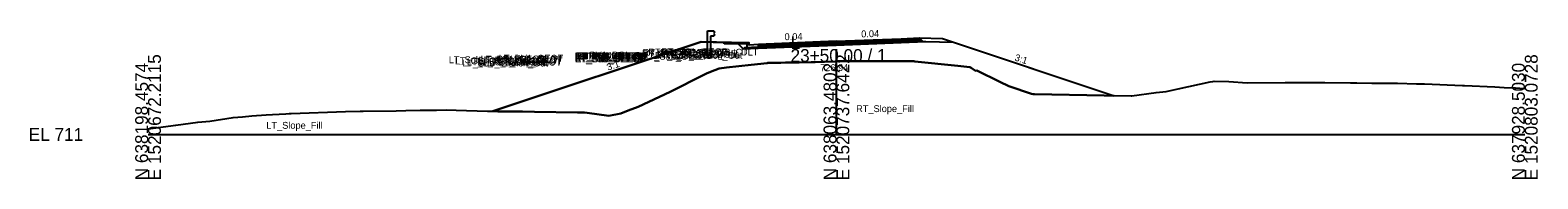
# Model space of a CAD drawing. Extents: x -26 to 3903, y -10 to 9531.
# Drawn here: x 974.3 to 1302.8, y 3490.3 to 3522.7 of the extents above; entities that cross this region are included whole.
import ezdxf

# ---------------------------------------------------------------- set-up
doc = ezdxf.new("R2010")
doc.units = 0
for name, color, linetype in [('Default', 7, 'Continuous'), ('Exist Cross Section Cell', 7, 'Continuous'), ('Exist XS Center Line Elevation Label', 7, 'Continuous'), ('Exist XS Ground Line', 7, 'Continuous'), ('Old_Level_63', 7, 'Continuous'), ('Prop CMT Conc Surface', 7, 'Continuous'), ('Prop CMT Guardrail Graphics', 7, 'Continuous'), ('Prop CMT Pvmt Course 1', 7, 'Continuous'), ('Prop CMT Pvmt Course 1 CG', 7, 'Continuous'), ('Prop CMT Pvmt Course 2', 7, 'Continuous'), ('Prop CMT Pvmt Course 3', 7, 'Continuous'), ('Prop CMT Pvmt Surface', 7, 'Continuous'), ('Prop CMT Pvmt Surface Shoulder', 7, 'Continuous'), ('Prop CMT Shld Paved Course 1', 7, 'Continuous'), ('Prop CMT Shld Paved Course 2', 7, 'Continuous'), ('Prop CMT Shld Paved Course 3', 7, 'Continuous'), ('Prop CMT Slope Grass', 7, 'Continuous'), ('Prop CMT Subgrade Earthwork', 7, 'Continuous'), ('Prop XS Earthwork Shape', 7, 'Continuous'), ('Prop XS Finish Grade Concrete', 7, 'Continuous'), ('Prop XS SE Text', 7, 'Continuous'), ('Prop XS Side Slope Text', 7, 'Continuous')]:
    doc.layers.add(name, color=color, linetype=linetype)

msp = doc.modelspace()

# ---------------------------------------------------------------- linework, layer by layer
at = {"layer": 'Exist Cross Section Cell'}
for p, q in [((1150, 3500), (1150, 3518.61)), ((1000, 3500), (1150, 3500)), ((1150, 3500), (1300, 3500))]:
    msp.add_line(p, q, dxfattribs=at)
at = {"layer": 'Exist XS Ground Line'}
msp.add_lwpolyline([(1000, 3501.2), (1006.06, 3502.04), (1010.87, 3502.66), (1013.43, 3502.91), (1018.58, 3503.68), (1020.58, 3503.83), (1022.59, 3504.07), (1025.76, 3504.25), (1027.11, 3504.34), (1030.01, 3504.49), (1030.72, 3504.53), (1031.16, 3504.55), (1042.99, 3504.97), (1046.22, 3505.08), (1046.5, 3505.1), (1046.84, 3505.1), (1054.04, 3505.17), (1056.16, 3505.22), (1059.32, 3505.26), (1062.82, 3505.3), (1065.04, 3505.34), (1067.17, 3505.32), (1073.96, 3505.09), (1074.47, 3505.07), (1075.61, 3505.05), (1076.21, 3504.99), (1081.61, 3504.99), (1084.22, 3504.94), (1093.59, 3504.81), (1095.09, 3504.8), (1095.69, 3504.69), (1100.44, 3504.03), (1103.05, 3504.6), (1104.65, 3505.19), (1106.77, 3506.03), (1113.74, 3509.28), (1121.12, 3513), (1121.81, 3513.39), (1123.53, 3514.03), (1124.47, 3514.39), (1126.04, 3514.59), (1131.41, 3515.19), (1134.91, 3515.57), (1135.05, 3515.58), (1135.54, 3515.6), (1135.84, 3515.6), (1136.08, 3515.61), (1136.12, 3515.62), (1136.35, 3515.62), (1137.86, 3515.64), (1138.9, 3515.66), (1139.73, 3515.67), (1141.48, 3515.7), (1141.62, 3515.7), (1141.7, 3515.7), (1141.9, 3515.71), (1144.46, 3515.77), (1145.36, 3515.79), (1147.19, 3515.85), (1147.23, 3515.85), (1147.25, 3515.85), (1147.4, 3515.86), (1149.82, 3515.94), (1149.93, 3515.95), (1150.16, 3515.95), (1152.79, 3515.96), (1152.9, 3515.96), (1155.55, 3515.96), (1158.04, 3515.98), (1158.32, 3515.98), (1158.41, 3515.98), (1158.61, 3515.98), (1160.29, 3515.97), (1161.11, 3515.97), (1163.46, 3515.98), (1163.89, 3515.98), (1163.93, 3515.98), (1164.31, 3515.97), (1165.32, 3515.97), (1166.69, 3515.96), (1166.83, 3515.96), (1167.06, 3515.94), (1176.42, 3514.99), (1179.08, 3514.64), (1179.33, 3514.54), (1180.31, 3513.85), (1180.58, 3513.97), (1185.58, 3511.49), (1187.55, 3510.52), (1192.54, 3508.86), (1192.76, 3508.81), (1193.17, 3508.79), (1208.34, 3508.46), (1214.24, 3508.43), (1214.35, 3508.43), (1219.67, 3509.11), (1221.85, 3509.35), (1224.5, 3509.91), (1231.41, 3511.45), (1231.99, 3511.57), (1232.28, 3511.63), (1235.47, 3511.56), (1239.5, 3511.27), (1247.81, 3511.36), (1251.2, 3511.35), (1256.37, 3511.36), (1256.39, 3511.36), (1262.02, 3511.25), (1263.4, 3511.23), (1266.66, 3511.2), (1268.29, 3511.19), (1272.27, 3511.16), (1276.41, 3511.05), (1278.15, 3511.01), (1286.39, 3510.68), (1286.83, 3510.66), (1293.46, 3510.36), (1293.5, 3510.36), (1295.47, 3510.26), (1297.88, 3510.14), (1297.99, 3510.13), (1298.91, 3510.09), (1300, 3510.04)], dxfattribs=at)
at = {"layer": 'Old_Level_63'}
for p, q in [((1131, 3519.47), (1131, 3519.97)), ((1133, 3519.63), (1131, 3519.47))]:
    msp.add_line(p, q, dxfattribs=at)
for points in [[(1125.5, 3519.75), (1125.5, 3520.07)], [(1130.5, 3519.65), (1125.5, 3519.75)], [(1130.5, 3519.97), (1130.5, 3518.95), (1133, 3519.05)], [(1133, 3519.05), (1133, 3519.63)]]:
    msp.add_lwpolyline(points, dxfattribs=at)
at = {"layer": 'Prop CMT Guardrail Graphics'}
for points in [[(1121.9, 3516.62), (1121.9, 3522.62)], [(1121.9, 3522.62), (1123.23, 3522.62), (1123.5, 3522.33)], [(1123.5, 3522.33), (1123.23, 3522.03)], [(1123.23, 3522.03), (1123.5, 3521.74)], [(1123.5, 3521.74), (1123.23, 3521.45), (1122.56, 3521.45)], [(1122.56, 3521.45), (1122.56, 3516.62)], [(1122.56, 3516.62), (1121.9, 3516.62)]]:
    msp.add_lwpolyline(points, dxfattribs=at)
at = {"layer": 'Prop CMT Pvmt Course 1'}
for points in [[(1149.97, 3520.31), (1133, 3519.63)], [(1133, 3519.38), (1149.97, 3520.06)], [(1133, 3519.63), (1133, 3519.38)], [(1149.97, 3520.31), (1164.08, 3520.87)], [(1164.08, 3520.62), (1149.97, 3520.06)], [(1149.97, 3520.06), (1149.97, 3520.31)], [(1149.97, 3520.06), (1149.97, 3520.31)], [(1164.08, 3520.87), (1164.08, 3520.62)]]:
    msp.add_lwpolyline(points, dxfattribs=at)
msp.add_lwpolyline([(1149.97, 3520.06), (1149.97, 3520.18), (1149.97, 3520.18), (1149.97, 3520.06)], close=True, dxfattribs=at)
msp.add_lwpolyline([(1149.97, 3520.06), (1149.97, 3520.18), (1149.97, 3520.18), (1149.97, 3520.06)], close=True, dxfattribs=at)
at = {"layer": 'Prop CMT Pvmt Course 1 CG'}
for points in [[(1133, 3519.05), (1129.96, 3518.92), (1129.7, 3518.66)], [(1129.7, 3518.66), (1132.96, 3518.79)], [(1133, 3518.8), (1133, 3519.05)]]:
    msp.add_lwpolyline(points, dxfattribs=at)
at = {"layer": 'Prop CMT Pvmt Course 2'}
for points in [[(1149.97, 3520.06), (1133, 3519.38)], [(1133, 3519.05), (1149.97, 3519.72)], [(1133, 3519.38), (1133, 3519.05)], [(1149.97, 3520.06), (1164.08, 3520.62)], [(1164.08, 3520.29), (1149.97, 3519.72)], [(1149.97, 3519.72), (1149.97, 3520.06)], [(1149.97, 3519.72), (1149.97, 3520.06)], [(1164.08, 3520.62), (1164.08, 3520.29)]]:
    msp.add_lwpolyline(points, dxfattribs=at)
at = {"layer": 'Prop CMT Pvmt Course 3'}
for points in [[(1132.63, 3518.78), (1149.97, 3519.47)], [(1149.97, 3519.72), (1133, 3519.05)], [(1133, 3519.05), (1133, 3518.8)], [(1149.97, 3519.72), (1164.08, 3520.29)], [(1164.08, 3520.04), (1149.97, 3519.47)], [(1149.97, 3519.47), (1149.97, 3519.72)], [(1149.97, 3519.47), (1149.97, 3519.72)], [(1164.08, 3520.29), (1164.08, 3520.04)]]:
    msp.add_lwpolyline(points, dxfattribs=at)
at = {"layer": 'Prop CMT Pvmt Surface'}
for points in [[(1149.97, 3520.31), (1133, 3519.63)], [(1149.97, 3520.31), (1164.08, 3520.87)]]:
    msp.add_lwpolyline(points, dxfattribs=at)
at = {"layer": 'Prop CMT Pvmt Surface Shoulder'}
msp.add_lwpolyline([(1164.08, 3520.87), (1168.08, 3521.03)], dxfattribs=at)
at = {"layer": 'Prop CMT Shld Paved Course 1'}
for points in [[(1164.08, 3520.87), (1168.08, 3521.03), (1168.32, 3520.79)], [(1164.08, 3520.62), (1164.08, 3520.87)], [(1168.32, 3520.79), (1164.08, 3520.62)]]:
    msp.add_lwpolyline(points, dxfattribs=at)
at = {"layer": 'Prop CMT Shld Paved Course 2'}
for points in [[(1164.08, 3520.62), (1168.32, 3520.79), (1168.64, 3520.47)], [(1164.08, 3520.29), (1164.08, 3520.62)], [(1168.64, 3520.47), (1164.08, 3520.29)]]:
    msp.add_lwpolyline(points, dxfattribs=at)
at = {"layer": 'Prop CMT Shld Paved Course 3'}
for points in [[(1164.08, 3520.29), (1168.64, 3520.47), (1168.88, 3520.23)], [(1164.08, 3520.04), (1164.08, 3520.29)], [(1169.38, 3520.25), (1164.08, 3520.04)]]:
    msp.add_lwpolyline(points, dxfattribs=at)
at = {"layer": 'Prop CMT Slope Grass'}
msp.add_line((1130.5, 3519.97), (1120.5, 3520.17), dxfattribs=at)
for points in [[(1120.5, 3520.17), (1075.16, 3505.06)], [(1168.08, 3521.03), (1173.08, 3520.93), (1210.52, 3508.45)]]:
    msp.add_lwpolyline(points, dxfattribs=at)
at = {"layer": 'Prop CMT Subgrade Earthwork'}
for points in [[(1132.96, 3518.79), (1129.7, 3518.66), (1128.35, 3520.01)], [(1149.97, 3519.47), (1132.63, 3518.78)], [(1149.97, 3519.47), (1164.08, 3520.04)], [(1164.08, 3520.04), (1169.38, 3520.25)], [(1169.38, 3520.25), (1175.49, 3520.13)]]:
    msp.add_lwpolyline(points, dxfattribs=at)
at = {"layer": 'Prop XS Earthwork Shape'}
for points in [[(1129.7, 3518.66), (1132.63, 3518.78), (1132.96, 3518.79), (1149.97, 3519.47), (1164.08, 3520.04), (1169.38, 3520.25), (1175.49, 3520.13), (1210.52, 3508.45), (1208.34, 3508.46), (1193.17, 3508.79), (1192.76, 3508.81), (1192.54, 3508.86), (1187.55, 3510.52), (1185.58, 3511.49), (1180.58, 3513.97), (1180.31, 3513.85), (1179.33, 3514.54), (1179.08, 3514.64), (1176.42, 3514.99), (1167.06, 3515.94), (1166.83, 3515.96), (1166.69, 3515.96), (1165.32, 3515.97), (1164.31, 3515.97), (1163.89, 3515.98), (1163.46, 3515.98), (1161.11, 3515.97), (1160.29, 3515.97), (1158.61, 3515.98), (1158.32, 3515.98), (1158.04, 3515.98), (1155.55, 3515.96), (1152.9, 3515.96), (1152.79, 3515.96), (1150.16, 3515.95), (1149.93, 3515.95), (1149.82, 3515.94), (1147.4, 3515.86), (1147.19, 3515.85), (1145.36, 3515.79), (1144.46, 3515.77), (1141.9, 3515.71), (1141.7, 3515.7), (1141.48, 3515.7), (1139.73, 3515.67), (1138.9, 3515.66), (1137.86, 3515.64), (1136.35, 3515.62), (1136.12, 3515.62), (1135.84, 3515.6), (1135.54, 3515.6), (1135.05, 3515.58), (1134.91, 3515.57), (1131.41, 3515.19), (1126.04, 3514.59), (1124.47, 3514.39), (1123.53, 3514.03), (1121.81, 3513.39), (1121.12, 3513), (1113.74, 3509.28), (1106.77, 3506.03), (1104.65, 3505.19), (1103.05, 3504.6), (1100.44, 3504.03), (1095.69, 3504.69), (1095.09, 3504.8), (1093.59, 3504.81), (1084.22, 3504.94), (1081.61, 3504.99), (1076.21, 3504.99), (1075.61, 3505.05), (1075.16, 3505.06), (1120.5, 3520.17), (1128.35, 3520.01)], [(1132.96, 3518.79), (1149.97, 3519.47), (1164.08, 3520.04), (1169.38, 3520.25), (1175.49, 3520.13), (1210.52, 3508.45), (1208.34, 3508.46), (1193.17, 3508.79), (1192.76, 3508.81), (1192.54, 3508.86), (1187.55, 3510.52), (1185.58, 3511.49), (1180.58, 3513.97), (1180.31, 3513.85), (1179.33, 3514.54), (1179.08, 3514.64), (1176.42, 3514.99), (1167.06, 3515.94), (1166.83, 3515.96), (1166.69, 3515.96), (1165.32, 3515.97), (1164.31, 3515.97), (1163.89, 3515.98), (1163.46, 3515.98), (1161.11, 3515.97), (1160.29, 3515.97), (1158.61, 3515.98), (1158.32, 3515.98), (1158.04, 3515.98), (1155.55, 3515.96), (1152.9, 3515.96), (1152.79, 3515.96), (1150.16, 3515.95), (1149.93, 3515.95), (1149.82, 3515.94), (1147.4, 3515.86), (1147.19, 3515.85), (1145.36, 3515.79), (1144.46, 3515.77), (1141.9, 3515.71), (1141.7, 3515.7), (1141.48, 3515.7), (1139.73, 3515.67), (1138.9, 3515.66), (1137.86, 3515.64), (1136.35, 3515.62), (1136.12, 3515.62), (1135.84, 3515.6), (1135.54, 3515.6), (1135.05, 3515.58), (1134.91, 3515.57), (1131.41, 3515.19), (1126.04, 3514.59), (1124.47, 3514.39), (1123.53, 3514.03), (1121.81, 3513.39), (1121.12, 3513), (1113.74, 3509.28), (1106.77, 3506.03), (1104.65, 3505.19), (1103.05, 3504.6), (1100.44, 3504.03), (1095.69, 3504.69), (1095.09, 3504.8), (1093.59, 3504.81), (1084.22, 3504.94), (1081.61, 3504.99), (1076.21, 3504.99), (1075.61, 3505.05), (1075.16, 3505.06), (1120.5, 3520.17), (1128.35, 3520.01), (1129.7, 3518.66), (1132.63, 3518.78)]]:
    msp.add_lwpolyline(points, close=True, dxfattribs=at)
at = {"layer": 'Prop XS Finish Grade Concrete'}
msp.add_lwpolyline([(1133, 3519.63), (1131, 3519.47), (1131, 3519.97), (1130.5, 3519.97)], dxfattribs=at)

# ---------------------------------------------------------------- texts
at = {"layer": 'Default'}
msp.add_text('-', height=0.0001, dxfattribs=at).set_placement((1000, 3500))
at = {"layer": 'Exist Cross Section Cell'}
for s, p in [('23+50.00 / 1', (1140, 3515.81)), ('L', (1140, 3518.61)), ('EL 711', (974, 3498.6))]:
    msp.add_text(s, height=2.8, dxfattribs=at).set_placement(p)
for s, p in [('N 638198.4574', (1000, 3490)), ('E 1520672.2115', (1002.8, 3490)), ('N 638063.4802', (1150, 3490)), ('E 1520737.6422', (1152.8, 3490)), ('N 637928.5030', (1300, 3490)), ('E 1520803.0728', (1302.8, 3490))]:
    msp.add_text(s, height=2.8, rotation=90, dxfattribs=at).set_placement(p)
at = {"layer": 'Exist XS Center Line Elevation Label'}
msp.add_text('726.94', height=1.5, rotation=0.8401, dxfattribs=at).set_placement((1146.47, 3513.77))
at = {"layer": 'Prop CMT Conc Surface'}
for s, p in [('RT_PV1_OEOT', (1107.79, 3517.12)), ('RT_Sub_Trench_Out_DLT', (1109.01, 3517.24)), ('RT_PS1_OEOP', (1111.85, 3517.28)), ('RT_GS_OS_CTL', (1116.19, 3517.18)), ('LT_Sub_Trench_Out_DLT', (1065.52, 3515.54)), ('LT_GS_OS_CTL', (1066.83, 3515.3)), ('LT_Sub_Trench_Out', (1068.43, 3514.82)), ('LT_PS3_Shelf_Out', (1069.51, 3515.08)), ('LT_PS3_OEOP', (1071.71, 3515.1)), ('LT_PS2_OEOP', (1072.05, 3515.44)), ('LT_PS1_OEOP', (1072.49, 3515.7)), ('LT_PV2_OEOT', (1076.25, 3515.61)), ('LT_PV3_OEOT', (1076.25, 3515.28)), ('LT_Sub_OEOT', (1076.29, 3515.03)), ('LT_PV1_OEOT', (1076.43, 3515.86)), ('RT_PV2_OEEOP', (1092.97, 3516.31)), ('RT_PV3_OEEOP', (1092.97, 3515.97)), ('RT_Sub_OEEOP', (1093.01, 3515.72)), ('LT_PV2_OEEOP', (1093.06, 3516.31)), ('LT_PV3_OEEOP', (1093.06, 3515.97)), ('LT_Sub_OEEOP', (1093.1, 3515.72)), ('RT_PV1_OEEOP', (1093.15, 3516.43)), ('LT_PV1_OEEOP', (1093.24, 3516.43)), ('RT_PV2_IEEOP', (1093.54, 3516.31)), ('LT_PV2_IEEOP', (1093.63, 3516.31)), ('RT_PV1_IEEOP', (1093.72, 3516.43)), ('LT_PV1_IEEOP', (1093.81, 3516.43)), ('PV2_PGL', (1096, 3516.31)), ('PV1_PGL', (1096.18, 3516.56)), ('RT_PV2_OEOT', (1107.61, 3516.87)), ('RT_PV3_OEOT', (1107.61, 3516.54)), ('RT_Sub_OEOT', (1107.65, 3516.29)), ('RT_Sub_Trench_Out', (1110.46, 3516.5)), ('RT_PS3_Shelf_Out', (1111.04, 3516.74)), ('RT_PS2_OEOP', (1111.91, 3517.04)), ('RT_PS3_OEOP', (1112.23, 3516.72)), ('RT_Slope_Fill', (1154.29, 3504.87)), ('LT_Slope_Fill', (1025.77, 3501.23))]:
    msp.add_text(s, height=1.5, dxfattribs=at).set_placement(p)
at = {"layer": 'Prop XS SE Text'}
for p in [(1138.71, 3520.55), (1155.41, 3521.17)]:
    msp.add_text('0.04', height=1.5, rotation=1.1458, dxfattribs=at).set_placement(p)
at = {"layer": 'Prop XS Side Slope Text'}
for rotation, p in [(18.4332, (1100.23, 3513.89)), (341.5668, (1188.71, 3516.16))]:
    msp.add_text('3:1', height=1.5, rotation=rotation, dxfattribs=at).set_placement(p)

doc.saveas('drawing.dxf')
